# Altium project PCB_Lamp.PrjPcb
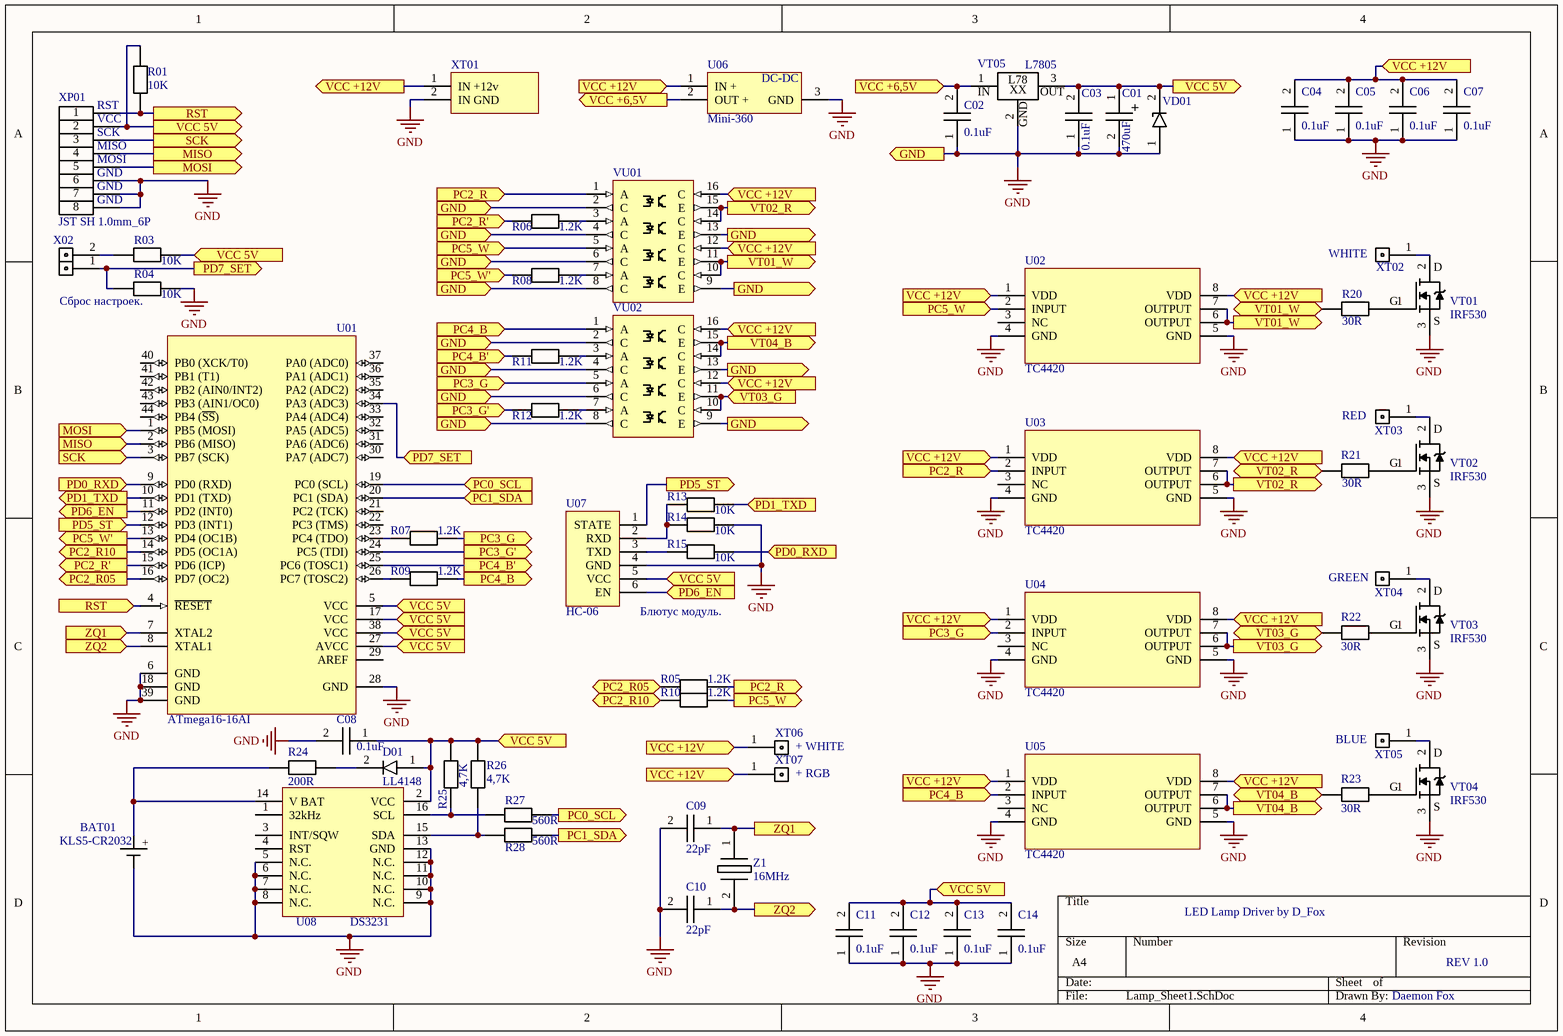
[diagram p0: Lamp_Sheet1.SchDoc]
1 sheet, 65 parts. Net scope: flat (ports and power ports of the same name join across sheets).
Board file: Lamp_PCB1.PcbDoc

## Sheet Lamp_Sheet1.SchDoc
size A4

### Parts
BAT01  KLS5-CR2032  [KLS5-CR2032]
C01  470uF  [cap_tantalum_d]
C02  0.1uF  [CAP_0805]
C03  0.1uF  [CAP_0805]
C04  0.1uF  [CAP_0805]
C05  0.1uF  [CAP_0805]
C06  0.1uF  [CAP_0805]
C07  0.1uF  [CAP_0805]
C08  0.1uF  [CAP_0805]
C09  22pF  [CAP_0805]
C10  22pF  [CAP_0805]
C11  0.1uF  [CAP_0805]
C12  0.1uF  [CAP_0805]
C13  0.1uF  [CAP_0805]
C14  0.1uF  [CAP_0805]
D01  LL4148  [LL4148]
R01  10K  [RES_0805]
R03  10K  [RES_0805]
R04  10K  [RES_0805]
R05  1.2K  [RES_0805]
R06  1.2K  [RES_0805]
R07  1.2K  [RES_0805]
R08  1.2K  [RES_0805]
R09  1.2K  [RES_0805]
R10  1.2K  [RES_0805]
R11  1.2K  [RES_0805]
R12  1.2K  [RES_0805]
R13  10K  [RES_0805]
R14  10K  [RES_0805]
R15  10K  [RES_0805]
R20  30R  [RES_1206]
R21  30R  [RES_1206]
R22  30R  [RES_1206]
R23  30R  [RES_1206]
R24  200R  [RES_0805]
R25  4,7K  [RES_0805]
R26  4,7K  [RES_0805]
R27  560R  [RES_0805]
R28  560R  [RES_0805]
U01  ATmega16-16AI  [My_44A_M]
U02  TC4420  [ATtiny13A]
U03  TC4420  [ATtiny13A]
U04  TC4420  [ATtiny13A]
U05  TC4420  [ATtiny13A]
U06  Mini-360  [Mini-360]
U07  HC-06  [HC-05/06]
U08  DS3231_DUP  [DS3231]  (value not drawn)
VD01  SMBJ5.0A  [SMBJ5.0A]  (value not drawn)
VT01  IRF530  [IRF530 - DUP]
VT02  IRF530  [IRF530 - DUP]
VT03  IRF530  [IRF530 - DUP]
VT04  IRF530  [IRF530 - DUP]
VT05  L7805  [L7805]
VU01  TLP281-4  [TLP281-4]  (value not drawn)
VU02  TLP281-4  [TLP281-4]  (value not drawn)
X02  PLS-2  [PLS-2 - DUP]  (value not drawn)
XP01  JST SH 1.0mm_6P  [JST SH 1.0mm 6P]
XT01  LED_12v_IN  [LED_12v_IN - DUP]  (value not drawn)
XT02  LED_12v_1  [LED_12v_1]  (value not drawn)
XT03  LED_12v_1  [LED_12v_1]  (value not drawn)
XT04  LED_12v_1  [LED_12v_1]  (value not drawn)
XT05  LED_12v_1  [LED_12v_1]  (value not drawn)
XT06  LED_12v_1  [LED_12v_1]  (value not drawn)
XT07  LED_12v_1  [LED_12v_1]  (value not drawn)
Z1  16MHz  [QUARTZ]

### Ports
GND (in), GND (out), MISO (in), MISO (out), MOSI (in), MOSI (out), PC0_SCL (in), PC0_SCL (out), PC1_SDA (in), PC1_SDA (out), PC2_R05 (in), PC2_R05 (out), PC2_R10 (in), PC2_R10 (out), PC2_R (in), PC2_R (out), PC2_R' (in), PC2_R' (out), PC3_G (in), PC3_G (out), PC3_G' (in), PC3_G' (out), PC4_B (in), PC4_B (out), PC4_B' (in), PC4_B' (out), PC5_W (in), PC5_W (out), PC5_W' (in), PC5_W' (out), PD0_RXD (in), PD1_TXD (in), PD1_TXD (out), PD5_ST (in), PD5_ST (out), PD6_EN (in), PD6_EN (out), PD7_SET (in), PD7_SET (out), RST (in), RST (out), SCK (in), SCK (out), VCC 5V (in), VCC 5V (out), VCC +6,5V (in), VCC +6,5V (out), VCC +12V (in), VCC +12V (out), VT01_W (in), VT01_W (out), VT02_R (in), VT02_R (out), VT03_G (in), VT03_G (out), VT04_B (in), VT04_B (out), ZQ1 (in), ZQ1 (out), ZQ2 (in), ZQ2 (out)

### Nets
GND: BAT01.2 C01.2 C02.1 C03.1 C04.1 C05.1 C06.1 C07.1 C08.2 C09.2 C10.2 C11.1 C12.1 C13.1 C14.1 R04.2 R14.2 U01.6(GND) U01.18(GND) U01.28(GND) U01.39(GND) U02.4(GND) U02.5(GND) U03.4(GND) U03.5(GND) U04.4(GND) U04.5(GND) U05.4(GND) U05.5(GND) U06.3(GND) U07.4(GND) U08.5(N.C.) U08.6(N.C.) U08.7(N.C.) U08.8(N.C.) U08.9(N.C.) U08.10(N.C.) U08.11(N.C.) U08.12(N.C.) U08.13(GND) VD01.1 VT01.3 VT02.3 VT03.3 VT04.3 VT05.2 VU01.2(C) VU01.4(C) VU01.6(C) VU01.8(C) VU01.9(E) VU01.13(E) VU02.2(C) VU02.4(C) VU02.6(C) VU02.8(C) VU02.9(E) VU02.13(E) XP01.6 XP01.7 XP01.8 XT01.2(IN_GND) ; port GND
NetBAT01_1: BAT01.1 R24.1 U08.14(V_BAT)
NetC01_1: C01.1 C03.2 C08.1 C11.2 C12.2 C13.2 C14.2 D01.1 R01.2 R03.2 R25.2 R26.2 U01.5(VCC) U01.17(VCC) U01.27(AVCC) U01.38(VCC) U07.5(VCC) U08.2(VCC) VD01.2 VT05.3 XP01.2 ; port VCC 5V
NetC02_2: C02.2 U06.2(OUT_+) VT05.1 ; port VCC +6,5V
NetC04_2: C04.2 C05.2 C06.2 C07.2 U02.1(VDD) U02.8(VDD) U03.1(VDD) U03.8(VDD) U04.1(VDD) U04.8(VDD) U05.1(VDD) U05.8(VDD) U06.1(IN_+) VU01.12(C) VU01.16(C) VU02.12(C) VU02.16(C) XT01.1(IN_+12v) XT06.1 XT07.1 ; port VCC +12V
NetC09_1: C09.1 U01.7(XTAL2) Z1.1 ; port ZQ1
NetC10_1: C10.1 U01.8(XTAL1) Z1.2 ; port ZQ2
NetD01_2: D01.2 R24.2
NetR01_1: R01.1 U01.4(~{RESET}) XP01.1 ; port RST
NetR03_1: R03.1 X02.2
NetR04_1: R04.1 U01.34(PA3_(ADC3)) X02.1 ; port PD7_SET
NetR05_1: R05.1 U01.16(PD7_(OC2)) ; port PC2_R05
NetR05_2: R05.2 U03.2(INPUT) VU01.1(A) ; port PC2_R
NetR06_1: R06.1 U01.15(PD6_(ICP)) ; port PC2_R'
NetR06_2: R06.2 VU01.3(A)
NetR07_1: R07.1 U01.23(PC4_(TDO))
NetR07_2: R07.2 U04.2(INPUT) VU02.5(A) ; port PC3_G
NetR08_1: R08.1 U01.13(PD4_(OC1B)) ; port PC5_W'
NetR08_2: R08.2 VU01.7(A)
NetR09_1: R09.1 U01.26(PC7_(TOSC2))
NetR09_2: R09.2 U05.2(INPUT) VU02.1(A) ; port PC4_B
NetR10_1: R10.1 U01.14(PD5_(OC1A)) ; port PC2_R10
NetR10_2: R10.2 U02.2(INPUT) VU01.5(A) ; port PC5_W
NetR11_1: R11.1 U01.25(PC6_(TOSC1)) ; port PC4_B'
NetR11_2: R11.2 VU02.3(A)
NetR12_1: R12.1 U01.24(PC5_(TDI)) ; port PC3_G'
NetR12_2: R12.2 VU02.7(A)
NetR13_1: R13.1 R14.1 U07.2(RXD)
NetR13_2: R13.2 U01.10(PD1_(TXD)) ; port PD1_TXD
NetR15_1: R15.1 U07.3(TXD)
NetR15_2: R15.2 U01.9(PD0_(RXD)) ; port PD0_RXD
NetR20_1: R20.1 U02.6(OUTPUT) U02.7(OUTPUT) VU01.10(C) VU01.11(E) ; port VT01_W
NetR20_2: R20.2 VT01.1
NetR21_1: R21.1 U03.6(OUTPUT) U03.7(OUTPUT) VU01.14(C) VU01.15(E) ; port VT02_R
NetR21_2: R21.2 VT02.1
NetR22_1: R22.1 U04.6(OUTPUT) U04.7(OUTPUT) VU02.10(C) VU02.11(E) ; port VT03_G
NetR22_2: R22.2 VT03.1
NetR23_1: R23.1 U05.6(OUTPUT) U05.7(OUTPUT) VU02.14(C) VU02.15(E) ; port VT04_B
NetR23_2: R23.2 VT04.1
NetR25_1: R25.1 R27.1 U08.16(SCL)
NetR26_1: R26.1 R28.1 U08.15(SDA)
NetR27_2: R27.2 U01.19(PC0_(SCL)) ; port PC0_SCL
NetR28_2: R28.2 U01.20(PC1_(SDA)) ; port PC1_SDA
NetU01_1: U01.1(PB5_(MOSI)) XP01.5 ; port MOSI
NetU01_2: U01.2(PB6_(MISO)) XP01.4 ; port MISO
NetU01_3: U01.3(PB7_(SCK)) XP01.3 ; port SCK
NetU01_11: U01.11(PD2_(INT0)) U07.6(EN) ; port PD6_EN
NetU01_12: U01.12(PD3_(INT1)) U07.1(STATE) ; port PD5_ST
NetVT01_2: VT01.2 XT02.1
NetVT02_2: VT02.2 XT03.1
NetVT03_2: VT03.2 XT04.1
NetVT04_2: VT04.2 XT05.1

Not connected (* = marked no-connect by the designer): U01 21(PC2_(TCK)) 22(PC3_(TMS)) 29(AREF) 30(PA7_(ADC7)) 31(PA6_(ADC6)) 32(PA5_(ADC5)) 33(PA4_(ADC4)) 35(PA2_(ADC2)) 36(PA1_(ADC1)) 37(PA0_(ADC0)) 40(PB0_(XCK/T0)) 41(PB1_(T1)) 42(PB2_(AIN0/INT2)) 43(PB3_(AIN1/OC0)) 44(PB4_(~{SS})); U02 3(NC); U03 3(NC); U04 3(NC); U05 3(NC); U08 1(32kHz) 3(INT/SQW) 4(RST)

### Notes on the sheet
- (near R04) Сброс настроек.
- WHITE
- RED
- GREEN
- (near U07) Блютус модуль.
- + WHITE
- + RGB
- BLUE
- LED Lamp Driver by D_Fox
- REV 1.0
- Daemon Fox

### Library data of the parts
BAT01 = KLS5-CR2032: Батарейный отсек на 1xCR2032
C01 = 470uF 10v_D: CAPACITOR Tantalium Type D 470uF 10v
C02 C03 C04 C05 C06 C07 C08 C09-C14 = CAP 0805: CAP 0805 SMD
D01 = LL4148: Diod SOD80 200mA 100V
R01 R03 R04 R05 R06 R07 R08 R09-R15 R24-R28 = RES 0805
R20-R23 = RES 1206: RES 1206 by DFox
U01 = ATmega16-16AI: AVR 16K Bytes of In-System Programmable Flash Memory
U02 U03 U04 U05 = TC4420: HIGH-SPEED MOSFET  DRIVERS
U06 = Mini-360: Mini360, понижающий модуль, с 4,75 в-23 в до 1 В-17 в, 17x11x3,8 мм
U07 = HC-05/06: Bluetooth модуль HC-06 slave; HC-05 master/slave.
U08 = DS3231_DUP: Часы реального времени
VD01 = SMBJ5.0A: Защитный диод, 500Вт, 5В, [DO-214AA]
VT01 VT02 VT03 VT04 = IRF530: IRF530 N-канал, 100в, 15А, TO-220AB
VT05 = L7805: Стабилизатор напряжения +5В, 1.5А, TO-220
XP01 = JST SH 1.0mm_6P: JST SH 1.0mm 6P
Z1 = QUARTZ: quartz crystal resonator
